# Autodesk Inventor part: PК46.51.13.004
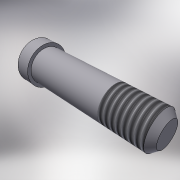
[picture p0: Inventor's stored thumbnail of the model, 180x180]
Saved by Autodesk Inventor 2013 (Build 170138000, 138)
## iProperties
Created: 2005-04
Part Number: PК46.51.13.004
Material: Stainless Steel, 440C
Document SubType Name: Modeling
Designer: =<Author>
Manufacturer: Standard
Standards Organization: Custom
Description: pin
Density: 7.75 g/cm^3
Mass: 25.2701 g
Surface Area: 14.5809 cm^2
Volume: 3.26065 cm^3
d0: 12.000 mm
d1: 10.000 mm
d2: 40.000 mm
d3: 35.000 mm
d5: 1.000 mm
d8: 13.000 mm
d9: 0.000 mm
d10: 1.600 mm
Author: PVitaliy
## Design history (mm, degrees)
sketch "Эскиз2"
  geometry: L1 (0, 0)-(47.162, 0); L2 (0, 0)-(0, 6); L3 (0, 6)-(5, 6); L4 (5, 6)-(5, 5); L5 (5, 5)-(40, 5); L6 (40, 5)-(40, 0); L7 (0, 0)-(40, 0)
  constraints: 14 end point, 3 parallel, 3 perpendicular, 1 horizontal, 1 point on line, 1 other
  dimensions: "d0" = 12 diameter of L3 L1; "d1" = 10 diameter of L5 L1; "d2" = 40 distance between parallel lines of L6 L2; "d3" = 35 distance between parallel lines of L4 L6
revolve "Вращение1" sketch "Эскиз2" stored, may be unused: angle "d4" = 90 deg
chamfer "Фаска1" distance "d5" = 1; stored, may be unused: second distance "d6" = 2, angle "d7" = 45 deg
feature "Резьба1" dims "d8" = 13, "d9" = 0
chamfer "Фаска2" distance "d10" = 1.6; stored, may be unused: second distance "d11" = 2, angle "d12" = 45 deg
body "Solid1"
